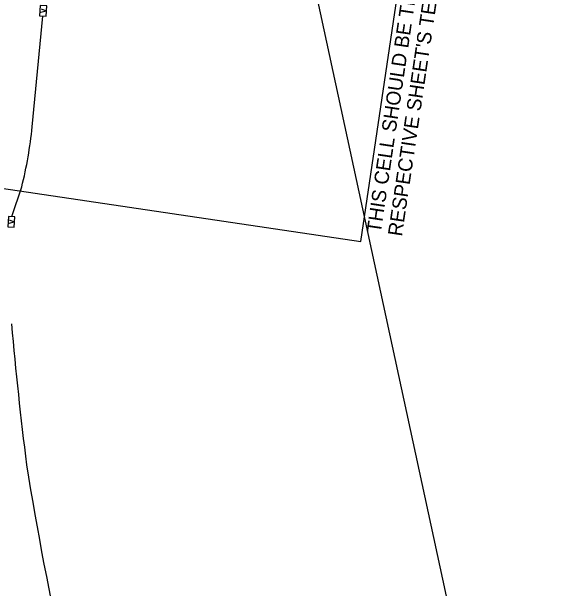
# Model space of a CAD drawing. Extents: x 601462 to 605493, y 331960 to 402715.
# Drawn here: x 602143 to 602828, y 354887 to 355593 of the extents above; entities that cross this region are included whole.
import ezdxf

# ---------------------------------------------------------------- set-up
doc = ezdxf.new("R2010")
doc.units = 0
for name, color, linetype in [('P_FTMS', 7, 'Continuous'), ('P_FTMSConduit', 7, 'Continuous'), ('P_MISC_TXT_2A (Construction)', 7, 'Continuous'), ('P_MISC_TXT_2B (Construction)', 7, 'Continuous')]:
    doc.layers.add(name, color=color, linetype=linetype)

# ---------------------------------------------------------------- blocks, each defined once
blk = doc.blocks.new('FTMS_FCV')
at = {"layer": 'P_FTMS'}
blk.add_line((12.7, 16.3), (0.6, -21.9), dxfattribs=at)
blk.add_lwpolyline([(39.1, 24.4), (-39.1, 24.4), (-39.1, -24.4), (39.1, -24.4)], close=True, dxfattribs=at)
blk.add_lwpolyline([(-12.1, 16.2), (0.6, -21.9)], dxfattribs=at)

msp = doc.modelspace()

# ---------------------------------------------------------------- linework, layer by layer
at = {"layer": 'P_FTMSConduit'}
for points in [[(602168.16, 355451.72), (602181.13, 355587.23)], [(602143.15, 355341.81), (602155.38, 355378.2)]]:
    msp.add_lwpolyline(points, dxfattribs=at)
for centre, radius, start, end in [((601670.53, 355500.38), 500, 345.85649, 354.41532), ((606343.83, 355570.74), 4216.31, 184.90359, 187.25923), ((606226.24, 355687.63), 4116.52, 189.08016, 202.81702)]:
    msp.add_arc(centre, radius, start, end, dxfattribs=at)
at = {"layer": 'P_MISC_TXT_2A (Construction)'}
msp.add_lwpolyline([(602570.08, 355311.27), (602801.22, 356869.22), (601836.78, 357012.31), (601605.64, 355454.36)], close=True, dxfattribs=at)
at = {"layer": 'P_MISC_TXT_2B (Construction)'}
msp.add_lwpolyline([(602827.66, 354169.05), (602495.48, 355708.62), (601542.42, 355502.99), (601874.59, 353963.42)], close=True, dxfattribs=at)

# ---------------------------------------------------------------- block references
at = {"layer": 'P_FTMS', "xscale": 0.1640416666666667, "yscale": 0.16404166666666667, "rotation": 86.34463929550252}
for p in [(602181.53, 355593.63), (602142.74, 355335.41)]:
    msp.add_blockref('FTMS_FCV', p, dxfattribs=at)

# ---------------------------------------------------------------- texts
at = {"layer": 'P_MISC_TXT_2A (Construction)'}
for s, p in [('THIS CELL SHOULD BE THE SAME COLOR AS THE', (602594.36, 355320.77)), ("RESPECTIVE SHEET'S TEXT IN THE TEXT FILE", (602620.33, 355316.92))]:
    msp.add_text(s, height=17.5, rotation=81.56113, dxfattribs=at).set_placement(p)

doc.saveas('drawing.dxf')
